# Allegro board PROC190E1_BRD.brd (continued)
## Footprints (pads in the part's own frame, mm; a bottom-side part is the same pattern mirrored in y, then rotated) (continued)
DIO_DFN0201_0-4
  rect 0.229x0.381 smd: 1(-0.22,0) 2(0.22,0)
DIO_DFN0402_0-5
  rect 0.356x0.61 smd: 1(-0.34,0) 2(0.34,0)
DIO_SOT23_123
  rect 1.016x0.61 smd: 1(-1.15,0.95) 2(-1.15,-0.95) 3(1.15,0)
DIO_SOT323-3_1-1
  rect 0.838x0.457 smd: 1(-1.05,0.65) 2(-1.05,-0.65) 3(1.05,0)
DSBGA12_15-74_60X70_0-4
  round 0.279 smd: A1(-0.4,0.6) A2(0,0.6) A3(0.4,0.6) B1(-0.4,0.2) B2(0,0.2) B3(0.4,0.2) C1(-0.4,-0.2) C2(0,-0.2) C3(0.4,-0.2) D1(-0.4,-0.6) D2(0,-0.6) D3(0.4,-0.6)
EMIFIL_BLM15A_0402_0-6
  rect 0.61x0.61 smd: 1(-0.46,0) 2(0.46,0)
EMIFIL_BLM18K_0603
  rect 0.94x1.194 smd: 1(-0.825,0) 2(0.825,0)
EMIFIL_BLM18P_0603_0-8
  rect 0.991x0.991 smd: 1(-0.75,0) 2(0.75,0)
HDR_1X2_90120-0122_S_T_5-6
  rect 1.702x1.702 hole 1.016: 1(0,0)
  round 1.702 hole 1.016: 2(-2.54,0)
HDR_1X2_61300211121_S_T_8-6
  rect 1.803x1.803 hole 1.118: 1(0,0)
  round 1.803 hole 1.118: 2(-2.54,0)
HDR_1X3_100_S_T
  rect 1.803x1.803 hole 1.118: 1(0,0)
  round 1.803 hole 1.118: 2(-2.54,0) 3(-5.08,0)
HDR_1X3_87224-3_S_T_10-8
  rect 1.6x1.6 hole 0.914: 1(0,0)
  round 1.6 hole 0.914: 2(-2.54,0) 3(-5.08,0)
HDR_2X4_90131-07_S_T_9-5
  rect 1.702x1.702 hole 1.016: 1(0,0)
  round 1.702 hole 1.016: 2(0,2.54) 3(2.54,0) 4(2.54,2.54) 5(5.08,0) 6(5.08,2.54) 7(7.62,0) 8(7.62,2.54)
HDR_2X5_PEC05DAAN_S_T_8-6
  rect 1.702x1.702 hole 1.016: 1(0,0)
  round 1.702 hole 1.016: 2(0,2.54) 3(2.54,0) 4(2.54,2.54) 5(5.08,0) 6(5.08,2.54) 7(7.62,0) 8(7.62,2.54) 9(10.16,0) 10(10.16,2.54)
HDR_2X10_FTR-110-51-D-06_S_S_8-7
  rect 0.711x3.124 smd: 1(-5.715,-2.578) 2(-5.715,2.578) 3(-4.445,-2.578) 4(-4.445,2.578) 5(-3.175,-2.578) 7(-1.905,-2.578) 8(-1.905,2.578) 9(-0.635,-2.578) 10(-0.635,2.578) 11(0.635,-2.578) 12(0.635,2.578) 13(1.905,-2.578) 14(1.905,2.578) 15(3.175,-2.578) 16(3.175,2.578) 17(4.445,-2.578) 18(4.445,2.578) 19(5.715,-2.578) 20(5.715,2.578)
HDR_6X2_100_S_T_5-5
  rect 1.702x1.702 hole 1.016: 1(0,0)
  round 1.702 hole 1.016: 2(0,2.54) 3(2.54,0) 4(2.54,2.54) 5(5.08,0) 6(5.08,2.54) 7(7.62,0) 8(7.62,2.54) 9(10.16,0) 10(10.16,2.54) 11(12.7,0) 12(12.7,2.54)
IND4_DLW21H_90X60_SMD_1-4
  rect 0.889x0.356 smd: 1(-0.85,-0.425) 2(0.85,-0.425) 3(0.85,0.425) 4(-0.85,0.425)
IND0806
  rect 1.219x1.803 smd: 1(-0.85,0) 2(0.85,0)
IND0806_1-2
  rect 1.219x1.803 smd: 1(-0.85,0) 2(0.85,0)
IND1210_1-2
  rect 1.346x2.794 smd: 1(-1.6,0) 2(1.6,0)
IND_XAL8080_330X350_SMD_8
  rect 1.778x7.01 smd: 1(-2.58,0) 2(2.58,0)
LED_150040GS73220_40X20_SMD_0-4
  rect 0.406x0.457 smd: 1(-0.5,0) 2(0.5,0)
LED_150080VS75000_80X50_SMD_0-8
  rect 1.092x1.194 smd: 1(-1.05,0) 2(1.05,0)
LED_150080VS75000_80X50_SMD_0-8#2
  rect 1.092x1.194 smd: 1(-1.05,0) 2(1.05,0)
LQFP64_19-68_390X390_1-6
  rect 1.499x0.305 smd: 1(-5.7,3.75) 2(-5.7,3.25) 3(-5.7,2.75) 4(-5.7,2.25) 5(-5.7,1.75) 6(-5.7,1.25) 7(-5.7,0.75) 8(-5.7,0.25) 9(-5.7,-0.25) 10(-5.7,-0.75) 11(-5.7,-1.25) 12(-5.7,-1.75) 13(-5.7,-2.25) 14(-5.7,-2.75) 15(-5.7,-3.25) 16(-5.7,-3.75) 33(5.7,-3.75) 34(5.7,-3.25) 35(5.7,-2.75) 36(5.7,-2.25) 37(5.7,-1.75) 38(5.7,-1.25) 39(5.7,-0.75) 40(5.7,-0.25) 41(5.7,0.25) 42(5.7,0.75) 43(5.7,1.25) 44(5.7,1.75) 45(5.7,2.25) 46(5.7,2.75) 47(5.7,3.25) 48(5.7,3.75)
  rect 0.305x1.499 smd: 17(-3.75,-5.7) 18(-3.25,-5.7) 19(-2.75,-5.7) 20(-2.25,-5.7) 21(-1.75,-5.7) 22(-1.25,-5.7) 23(-0.75,-5.7) 24(-0.25,-5.7) 25(0.25,-5.7) 26(0.75,-5.7) 27(1.25,-5.7) 28(1.75,-5.7) 29(2.25,-5.7) 30(2.75,-5.7) 31(3.25,-5.7) 32(3.75,-5.7) 49(3.75,5.7) 50(3.25,5.7) 51(2.75,5.7) 52(2.25,5.7) 53(1.75,5.7) 54(1.25,5.7) 55(0.75,5.7) 56(0.25,5.7) 57(-0.25,5.7) 58(-0.75,5.7) 59(-1.25,5.7) 60(-1.75,5.7) 61(-2.25,5.7) 62(-2.75,5.7) 63(-3.25,5.7) 64(-3.75,5.7)
MSOP8_25-59_125X125_1-1
  rect 1.448x0.457 smd: 1(-2.2,0.975) 2(-2.2,0.325) 3(-2.2,-0.325) 4(-2.2,-0.975) 5(2.2,-0.975) 6(2.2,-0.325) 7(2.2,0.325) 8(2.2,0.975)
MSOP10_19-68_120X120_1-1
  rect 1.448x0.305 smd: 1(-2.2,1) 2(-2.2,0.5) 3(-2.2,0) 4(-2.2,-0.5) 5(-2.2,-1) 6(2.2,-1) 7(2.2,-0.5) 8(2.2,0) 9(2.2,0.5) 10(2.2,1)
QFN24_19-68_220X140_1
  rect 0.838x0.279 smd: 1(-2.725,-0.75) 12(2.725,-0.75) 13(2.725,0.75) 24(-2.725,0.75)
  rect 0.279x0.838 smd: 2(-2.25,-1.725) 3(-1.75,-1.725) 4(-1.25,-1.725) 5(-0.75,-1.725) 6(-0.25,-1.725) 7(0.25,-1.725) 8(0.75,-1.725) 9(1.25,-1.725) 10(1.75,-1.725) 11(2.25,-1.725) 14(2.25,1.725) 15(1.75,1.725) 16(1.25,1.725) 17(0.75,1.725) 18(0.25,1.725) 19(-0.25,1.725) 20(-0.75,1.725) 21(-1.25,1.725) 22(-1.75,1.725) 23(-2.25,1.725)
  custom 0.508x0.508 smd: 25(0,0)
QFN24_TAD5212IRGER_160X160_1
  rect 0.787x0.305 smd: 1(-2,1.25) 2(-2,0.75) 3(-2,0.25) 4(-2,-0.25) 5(-2,-0.75) 6(-2,-1.25) 13(2,-1.25) 14(2,-0.75) 15(2,-0.25) 16(2,0.25) 17(2,0.75) 18(2,1.25)
  rect 0.305x0.787 smd: 7(-1.25,-2) 8(-0.75,-2) 9(-0.25,-2) 10(0.25,-2) 11(0.75,-2) 12(1.25,-2) 19(1.25,2) 20(0.75,2) 21(0.25,2) 22(-0.25,2) 23(-0.75,2) 24(-1.25,2)
  rect 2.21x2.21 smd: 25(0,0)
  rect 0.254x0.254 smd: A1(-1.725,1.725) A2(-1.725,-1.725) A3(1.725,-1.725) A4(1.725,1.725)
QFN32_19-68_200X200
  rect 0.838x0.305 smd: 1(-2.5,1.75) 2(-2.5,1.25) 3(-2.5,0.75) 4(-2.5,0.25) 5(-2.5,-0.25) 6(-2.5,-0.75) 7(-2.5,-1.25) 8(-2.5,-1.75) 17(2.5,-1.75) 18(2.5,-1.25) 19(2.5,-0.75) 20(2.5,-0.25) 21(2.5,0.25) 22(2.5,0.75) 23(2.5,1.25) 24(2.5,1.75)
  rect 0.305x0.838 smd: 9(-1.75,-2.5) 10(-1.25,-2.5) 11(-0.75,-2.5) 12(-0.25,-2.5) 13(0.25,-2.5) 14(0.75,-2.5) 15(1.25,-2.5) 16(1.75,-2.5) 25(1.75,2.5) 26(1.25,2.5) 27(0.75,2.5) 28(0.25,2.5) 29(-0.25,2.5) 30(-0.75,2.5) 31(-1.25,2.5) 32(-1.75,2.5)
  rect 3.556x3.556 smd: 33(0,0)
QFN32_19-68_200X200_0-8_EP3-6
  rect 0.787x0.305 smd: 1(-2.5,1.75) 2(-2.5,1.25) 3(-2.5,0.75) 4(-2.5,0.25) 5(-2.5,-0.25) 6(-2.5,-0.75) 7(-2.5,-1.25) 8(-2.5,-1.75) 17(2.5,-1.75) 18(2.5,-1.25) 19(2.5,-0.75) 20(2.5,-0.25) 21(2.5,0.25) 22(2.5,0.75) 23(2.5,1.25) 24(2.5,1.75)
  rect 0.305x0.787 smd: 9(-1.75,-2.5) 10(-1.25,-2.5) 11(-0.75,-2.5) 12(-0.25,-2.5) 13(0.25,-2.5) 14(0.75,-2.5) 15(1.25,-2.5) 16(1.75,-2.5) 25(1.75,2.5) 26(1.25,2.5) 27(0.75,2.5) 28(0.25,2.5) 29(-0.25,2.5) 30(-0.75,2.5) 31(-1.25,2.5) 32(-1.75,2.5)
  rect 3.607x3.607 smd: 33(0,0)
RES0201_0-5
  rect 0.356x0.33 smd: 1(-0.28,0) 2(0.28,0)
RES0402_0-5
  rect 0.559x0.635 smd: 1(-0.49,0) 2(0.49,0)
RES0603_0-5
  rect 0.635x0.991 smd: 1(-0.74,0) 2(0.74,0)
RES0603_0-75
  rect 0.635x0.991 smd: 1(-0.74,0) 2(0.74,0)
RES0805_0-75
  rect 1.194x1.448 smd: 1(-0.95,0) 2(0.95,0)
RES_CST0612_0612-4_0-9
  rect 0.991x2.311 smd: 1(-0.85,0.6) 4(0.85,0.6)
  rect 0.991x0.787 smd: 2(-0.85,-1.35) 3(0.85,-1.35)
RES_KRL3216T4_1206-4_0-7
  rect 1.143x0.356 smd: 1(-0.775,1.5) 4(0.775,1.5)
  rect 1.143x2.692 smd: 2(-0.775,-0.325) 3(0.775,-0.325)
RESA_EXB_0201-4_0-5
  rect 0.203x0.305 smd: 1(-0.6,-0.275) 2(-0.2,-0.275) 3(0.2,-0.275) 4(0.6,-0.275) 5(0.6,0.275) 6(0.2,0.275) 7(-0.2,0.275) 8(-0.6,0.275)
SC70-5
  rect 0.94x0.406 smd: 1(-1.1,0.65) 2(-1.1,0) 3(-1.1,-0.65) 4(1.1,-0.65) 5(1.1,0.65)
SC70-5_1-1
  rect 0.94x0.406 smd: 1(-1.1,0.65) 2(-1.1,0) 3(-1.1,-0.65) 4(1.1,-0.65) 5(1.1,0.65)
SC70-5_1-1#2
  rect 0.762x0.406 smd: 1(-1,0.65) 2(-1,0) 3(-1,-0.65) 4(1,-0.65) 5(1,0.65)
SC70-6_1-1
  rect 0.762x0.406 smd: 1(-1,0.65) 2(-1,0) 3(-1,-0.65) 4(1,-0.65) 5(1,0) 6(1,0.65)
SOIC8_1-8
  rect 1.549x0.61 smd: 1(-2.7,1.905) 2(-2.7,0.635) 3(-2.7,-0.635) 4(-2.7,-1.905) 5(2.7,-1.905) 6(2.7,-0.635) 7(2.7,0.635) 8(2.7,1.905)
SON6_19-68_40X60_PB_0-6
  rect 0.356x0.305 smd: 1(-0.3,0.5) 2(-0.3,0) 3(-0.3,-0.5) 4(0.3,-0.5) 5(0.3,0) 6(0.3,0.5)
SON6_25-59_85X85
  rect 0.61x0.356 smd: 1(-1.05,0.65) 2(-1.05,0) 3(-1.05,-0.65) 4(1.05,-0.65) 5(1.05,0) 6(1.05,0.65)
  rect 1.092x1.702 smd: 7(0,0)
SON6_25-59_85X85_0-8
  rect 0.61x0.356 smd: 1(-1.05,0.65) 2(-1.05,0) 3(-1.05,-0.65) 4(1.05,-0.65) 5(1.05,0) 6(1.05,0.65)
  rect 1.067x1.702 smd: 7(0,0)
SON6_25-59_85X85_0-8#2
  rect 0.61x0.356 smd: 1(-1.05,0.65) 2(-1.05,0) 3(-1.05,-0.65) 4(1.05,-0.65) 5(1.05,0) 6(1.05,0.65)
  rect 1.067x1.702 smd: 7(0,0)
SON6_CSD17313Q2_80X80
  rect 0.406x0.457 smd: 1(-0.65,-0.923) 2(0,-0.923) 3(0.65,-0.923) 4(0.65,0.923) 5(0,0.923) 6(-0.65,0.923)
  rect 0.406x0.864 smd: 7(0.65,0.096)
  rect 1.041x1.092 smd: 8(-0.325,0)
SON6_SN74LVC2G17_40X60_0-6
  rect 0.356x0.203 smd: 1(-0.275,0.5)
  rect 0.305x0.203 smd: 2(-0.3,0) 3(-0.3,-0.5) 4(0.3,-0.5) 5(0.3,0) 6(0.3,0.5)
SON8_25-59_130X130_1
  rect 0.762x0.356 smd: 1(-1.45,0.975) 2(-1.45,0.325) 3(-1.45,-0.325) 4(-1.45,-0.975) 5(1.45,-0.975) 6(1.45,-0.325) 7(1.45,0.325) 8(1.45,0.975)
  rect 1.753x2.515 smd: 9(0,0)
SOT23-5
  rect 0.889x0.559 smd: 1(-1.2,0.95) 2(-1.2,0) 3(-1.2,-0.95) 4(1.2,-0.95) 5(1.2,0.95)
SOT23-5#2
  rect 1.092x0.61 smd: 1(-1.3,0.95) 2(-1.3,0) 3(-1.3,-0.95) 4(1.3,-0.95) 5(1.3,0.95)
SOT23-5_1-5
  rect 1.092x0.61 smd: 1(-1.3,0.95) 2(-1.3,0) 3(-1.3,-0.95) 4(1.3,-0.95) 5(1.3,0.95)
SOT23-6
  rect 1.041x0.61 smd: 1(-1.35,0.95) 2(-1.35,0) 3(-1.35,-0.95) 4(1.35,-0.95) 5(1.35,0) 6(1.35,0.95)
SOT23-14_1-1
  rect 1.041x0.305 smd: 1(-1.5,1.5) 2(-1.5,1) 3(-1.5,0.5) 4(-1.5,0) 5(-1.5,-0.5) 6(-1.5,-1) 7(-1.5,-1.5) 8(1.5,-1.5) 9(1.5,-1) 10(1.5,-0.5) 11(1.5,0) 12(1.5,0.5) 13(1.5,1) 14(1.5,1.5)
SOT23-123_1-2
  rect 1.016x0.61 smd: 1(-1.15,0.95) 2(-1.15,-0.95) 3(1.15,0)
SOT553-5_0-6
  rect 0.559x0.229 smd: 1(-0.69,0.5) 2(-0.69,0) 3(-0.69,-0.5) 4(0.69,-0.5) 5(0.69,0.5)
SW3_CAS-120TA_215X100_SMD
  rect 1.6x1.016 smd: 1(-1.75,-1.15) 2(0,1.15) 3(1.75,-1.15)
SW4_49-99_150X230_SMD_2-7
  rect 0.762x1.27 smd: 1(-0.635,-3.81) 2(0.635,-3.81) 3(0.635,3.81) 4(-0.635,3.81)
SW4_100X216_200X200_SMD_4-2
  rect 1.27x1.27 smd: 1(-1.27,-2.75) 2(1.27,-2.75) 3(1.27,2.75) 4(-1.27,2.75)
SW4_100X216_200X200_SMD_4-2#2
  rect 1.27x1.27 smd: 1(-1.27,-2.75) 2(1.27,-2.75) 3(1.27,2.75) 4(-1.27,2.75)
SW16_416131160808_460X230_SMD_2-7
  rect 0.762x1.27 smd: 1(-4.445,-3.81) 2(-3.175,-3.81) 3(-1.905,-3.81) 4(-0.635,-3.81) 5(0.635,-3.81) 6(1.905,-3.81) 7(3.175,-3.81) 8(4.445,-3.81) 9(4.445,3.81) 10(3.175,3.81) 11(1.905,3.81) 12(0.635,3.81) 13(-0.635,3.81) 14(-1.905,3.81) 15(-3.175,3.81) 16(-4.445,3.81)
SW_TDA01H0S_240X90_SMD_2-3
  rect 1.27x0.762 smd: 1(-3.81,0) 2(3.81,0)
TO_SOT23-123
  rect 1.016x1.397 smd: 1(-0.95,-1.1) 2(0.95,-1.1) 3(0,1.1)
TP20_SMD
  round 0.508 smd: 1(0,0)
TP30_SMD
  round 0.762 smd: 1(0,0)
TP40_SMD
  round 1.016 smd: 1(0,0)
TP_40X65
  round 1.651 hole 1.016: 1(0,0)
TQFN42_19-68_140X360_0-8
  rect 0.813x0.305 smd: 1(-1.7,4) 2(-1.7,3.5) 3(-1.7,3) 4(-1.7,2.5) 5(-1.7,2) 6(-1.7,1.5) 7(-1.7,1) 8(-1.7,0.5) 9(-1.7,0) 10(-1.7,-0.5) 11(-1.7,-1) 12(-1.7,-1.5) 13(-1.7,-2) 14(-1.7,-2.5) 15(-1.7,-3) 16(-1.7,-3.5) 17(-1.7,-4) 22(1.7,-4) 23(1.7,-3.5) 24(1.7,-3) 25(1.7,-2.5) 26(1.7,-2) 27(1.7,-1.5) 28(1.7,-1) 29(1.7,-0.5) 30(1.7,0) 31(1.7,0.5) 32(1.7,1) 33(1.7,1.5) 34(1.7,2) 35(1.7,2.5) 36(1.7,3) 37(1.7,3.5) 38(1.7,4)
  rect 0.305x0.813 smd: 18(-0.75,-4.45) 19(-0.25,-4.45) 20(0.25,-4.45) 21(0.75,-4.45) 39(0.75,4.45) 40(0.25,4.45) 41(-0.25,4.45) 42(-0.75,4.45)
  rect 2.159x7.645 smd: 43(0,0)
TQFP128_15-74_550X550_1-2
  rect 1.499x0.203 smd: 1(-7.7,6.2) 2(-7.7,5.8) 3(-7.7,5.4) 4(-7.7,5) 5(-7.7,4.6) 6(-7.7,4.2) 7(-7.7,3.8) 8(-7.7,3.4) 9(-7.7,3) 10(-7.7,2.6) 11(-7.7,2.2) 12(-7.7,1.8) 13(-7.7,1.4) 14(-7.7,1) 15(-7.7,0.6) 16(-7.7,0.2) 17(-7.7,-0.2) 18(-7.7,-0.6) 19(-7.7,-1) 20(-7.7,-1.4) 21(-7.7,-1.8) 22(-7.7,-2.2) 23(-7.7,-2.6) 24(-7.7,-3) 25(-7.7,-3.4) 26(-7.7,-3.8) 27(-7.7,-4.2) 28(-7.7,-4.6) 29(-7.7,-5) 30(-7.7,-5.4) 31(-7.7,-5.8) 32(-7.7,-6.2) 65(7.7,-6.2) 66(7.7,-5.8) 67(7.7,-5.4) 68(7.7,-5) 69(7.7,-4.6) 70(7.7,-4.2) 71(7.7,-3.8) 72(7.7,-3.4) 73(7.7,-3) 74(7.7,-2.6) 75(7.7,-2.2) 76(7.7,-1.8) 77(7.7,-1.4) 78(7.7,-1) 79(7.7,-0.6) 80(7.7,-0.2) 81(7.7,0.2) 82(7.7,0.6) 83(7.7,1) 84(7.7,1.4) 85(7.7,1.8) 86(7.7,2.2) 87(7.7,2.6) 88(7.7,3) 89(7.7,3.4) 90(7.7,3.8) 91(7.7,4.2) 92(7.7,4.6) 93(7.7,5) 94(7.7,5.4) 95(7.7,5.8) 96(7.7,6.2)
  rect 0.203x1.499 smd: 33(-6.2,-7.7) 34(-5.8,-7.7) 35(-5.4,-7.7) 36(-5,-7.7) 37(-4.6,-7.7) 38(-4.2,-7.7) 39(-3.8,-7.7) 40(-3.4,-7.7) 41(-3,-7.7) 42(-2.6,-7.7) 43(-2.2,-7.7) 44(-1.8,-7.7) 45(-1.4,-7.7) 46(-1,-7.7) 47(-0.6,-7.7) 48(-0.2,-7.7) 49(0.2,-7.7) 50(0.6,-7.7) 51(1,-7.7) 52(1.4,-7.7) 53(1.8,-7.7) 54(2.2,-7.7) 55(2.6,-7.7) 56(3,-7.7) 57(3.4,-7.7) 58(3.8,-7.7) 59(4.2,-7.7) 60(4.6,-7.7) 61(5,-7.7) 62(5.4,-7.7) 63(5.8,-7.7) 64(6.2,-7.7) 97(6.2,7.7) 98(5.8,7.7) 99(5.4,7.7) 100(5,7.7) 101(4.6,7.7) 102(4.2,7.7) 103(3.8,7.7) 104(3.4,7.7) 105(3,7.7) 106(2.6,7.7) 107(2.2,7.7) 108(1.8,7.7) 109(1.4,7.7) 110(1,7.7) 111(0.6,7.7) 112(0.2,7.7) 113(-0.2,7.7) 114(-0.6,7.7) 115(-1,7.7) 116(-1.4,7.7) 117(-1.8,7.7) 118(-2.2,7.7) 119(-2.6,7.7) 120(-3,7.7) 121(-3.4,7.7) 122(-3.8,7.7) 123(-4.2,7.7) 124(-4.6,7.7) 125(-5,7.7) 126(-5.4,7.7) 127(-5.8,7.7) 128(-6.2,7.7)
TSSOP8_25-59_125X180_1-2
  rect 1.499x0.457 smd: 1(-2.9,0.975) 2(-2.9,0.325) 3(-2.9,-0.325) 4(-2.9,-0.975) 5(2.9,-0.975) 6(2.9,-0.325) 7(2.9,0.325) 8(2.9,0.975)
TSSOP14_25-59_205X180_1-2
  rect 1.499x0.457 smd: 1(-2.9,1.95) 2(-2.9,1.3) 3(-2.9,0.65) 4(-2.9,0) 5(-2.9,-0.65) 6(-2.9,-1.3) 7(-2.9,-1.95) 8(2.9,-1.95) 9(2.9,-1.3) 10(2.9,-0.65) 11(2.9,0) 12(2.9,0.65) 13(2.9,1.3) 14(2.9,1.95)
TSSOP20_25-59_260X180
  rect 1.499x0.457 smd: 1(-2.9,2.925) 2(-2.9,2.275) 3(-2.9,1.625) 4(-2.9,0.975) 5(-2.9,0.325) 6(-2.9,-0.325) 7(-2.9,-0.975) 8(-2.9,-1.625) 9(-2.9,-2.275) 10(-2.9,-2.925) 11(2.9,-2.925) 12(2.9,-2.275) 13(2.9,-1.625) 14(2.9,-0.975) 15(2.9,-0.325) 16(2.9,0.325) 17(2.9,0.975) 18(2.9,1.625) 19(2.9,2.275) 20(2.9,2.925)
TSSOP56_19-68_560X240_1-2
  rect 1.499x0.305 smd: 1(-3.75,6.75) 2(-3.75,6.25) 3(-3.75,5.75) 4(-3.75,5.25) 5(-3.75,4.75) 6(-3.75,4.25) 7(-3.75,3.75) 8(-3.75,3.25) 9(-3.75,2.75) 10(-3.75,2.25) 11(-3.75,1.75) 12(-3.75,1.25) 13(-3.75,0.75) 14(-3.75,0.25) 15(-3.75,-0.25) 16(-3.75,-0.75) 17(-3.75,-1.25) 18(-3.75,-1.75) 19(-3.75,-2.25) 20(-3.75,-2.75) 21(-3.75,-3.25) 22(-3.75,-3.75) 23(-3.75,-4.25) 24(-3.75,-4.75) 25(-3.75,-5.25) 26(-3.75,-5.75) 27(-3.75,-6.25) 28(-3.75,-6.75) 29(3.75,-6.75) 30(3.75,-6.25) 31(3.75,-5.75) 32(3.75,-5.25) 33(3.75,-4.75) 34(3.75,-4.25) 35(3.75,-3.75) 36(3.75,-3.25) 37(3.75,-2.75) 38(3.75,-2.25) 39(3.75,-1.75) 40(3.75,-1.25) 41(3.75,-0.75) 42(3.75,-0.25) 43(3.75,0.25) 44(3.75,0.75) 45(3.75,1.25) 46(3.75,1.75) 47(3.75,2.25) 48(3.75,2.75) 49(3.75,3.25) 50(3.75,3.75) 51(3.75,4.25) 52(3.75,4.75) 53(3.75,5.25) 54(3.75,5.75) 55(3.75,6.25) 56(3.75,6.75)
TVSOP14_15-74_180X150_1-2
  rect 1.499x0.203 smd: 1(-2.9,1.2) 2(-2.9,0.8) 3(-2.9,0.4) 4(-2.9,0) 5(-2.9,-0.4) 6(-2.9,-0.8) 7(-2.9,-1.2) 8(2.9,-1.2) 9(2.9,-0.8) 10(2.9,-0.4) 11(2.9,0) 12(2.9,0.4) 13(2.9,0.8) 14(2.9,1.2)
unnamed
  round 3.073 hole 3.2 unplated: (0,0)
unnamed#2
  round 0.686 hole 0.813 unplated: (-1.27,1.076) (0,1.076) (1.27,1.076)
UQFN10_19-68_80X60_0-6
  rect 0.584x0.305 smd: 1(-0.635,0.75) 4(-0.635,-0.75) 6(0.635,-0.75) 9(0.635,0.75)
  rect 0.584x0.254 smd: 2(-0.635,0.25) 3(-0.635,-0.25) 7(0.635,-0.25) 8(0.635,0.25)
  rect 0.305x0.635 smd: 5(0,-0.86) 10(0,0.86)
UQFN16_TMUX1574_70X100_0-6
  rect 0.711x0.203 smd: 1(-0.75,0.6)
  rect 0.61x0.203 smd: 2(-0.8,0.2) 3(-0.8,-0.2) 4(-0.8,-0.6) 9(0.8,-0.6) 10(0.8,-0.2) 11(0.8,0.2) 12(0.8,0.6)
  rect 0.203x0.61 smd: 5(-0.6,-1.2) 6(-0.2,-1.2) 7(0.2,-1.2) 8(0.6,-1.2) 13(0.6,1.2) 14(0.2,1.2) 15(-0.2,1.2) 16(-0.6,1.2)
UQFN16_TMUX1574_70X100_0-6#2
  rect 0.711x0.203 smd: 1(-0.75,0.6)
  rect 0.61x0.203 smd: 2(-0.8,0.2) 3(-0.8,-0.2) 4(-0.8,-0.6) 9(0.8,-0.6) 10(0.8,-0.2) 11(0.8,0.2) 12(0.8,0.6)
  rect 0.203x0.61 smd: 5(-0.6,-1.2) 6(-0.2,-1.2) 7(0.2,-1.2) 8(0.6,-1.2) 13(0.6,1.2) 14(0.2,1.2) 15(-0.2,1.2) 16(-0.6,1.2)
USON10_TMUX1204_40X100_0-6
  rect 0.559x0.203 smd: 1(-0.417,1) 2(-0.417,0.5) 4(-0.417,-0.5) 5(-0.417,-1) 6(0.417,-1) 7(0.417,-0.5) 9(0.417,0.5) 10(0.417,1)
  rect 0.559x0.406 smd: 3(-0.417,0) 8(0.417,0)
USON10_TPD4E05U_40X100_0-6
  rect 0.559x0.305 smd: 1(-0.385,1) 2(-0.385,0.5) 4(-0.385,-0.5) 5(-0.385,-1) 6(0.385,-1) 7(0.385,-0.5) 9(0.385,0.5) 10(0.385,1)
  rect 0.559x0.406 smd: 3(-0.385,0) 8(0.385,0)
VFBGA153_19-68_460X520_0-9
  round 0.203 smd: A1(-3.25,3.25) A2(-2.75,3.25) A3(-2.25,3.25) A4(-1.75,3.25) A5(-1.25,3.25) A6(-0.75,3.25) B1(-3.25,2.75) C1(-3.25,2.25) D1(-3.25,1.75) M1(-3.25,-2.25) N1(-3.25,-2.75) P1(-3.25,-3.25)
  round 0.254 smd: A7(-0.25,3.25) A8(0.25,3.25) A9(0.75,3.25) A10(1.25,3.25) A11(1.75,3.25) A12(2.25,3.25) A13(2.75,3.25) A14(3.25,3.25) B2(-2.75,2.75) B3(-2.25,2.75) B4(-1.75,2.75) B5(-1.25,2.75) B6(-0.75,2.75) B7(-0.25,2.75) B8(0.25,2.75) B9(0.75,2.75) B10(1.25,2.75) B11(1.75,2.75) B12(2.25,2.75) B13(2.75,2.75) B14(3.25,2.75) C2(-2.75,2.25) C3(-2.25,2.25) C4(-1.75,2.25) C5(-1.25,2.25) C6(-0.75,2.25) C7(-0.25,2.25) C8(0.25,2.25) C9(0.75,2.25) C10(1.25,2.25) C11(1.75,2.25) C12(2.25,2.25) C13(2.75,2.25) C14(3.25,2.25) D2(-2.75,1.75) D3(-2.25,1.75) D4(-1.75,1.75) D12(2.25,1.75) D13(2.75,1.75) D14(3.25,1.75) E1(-3.25,1.25) E2(-2.75,1.25) E3(-2.25,1.25) E5(-1.25,1.25) E6(-0.75,1.25) E7(-0.25,1.25) E8(0.25,1.25) E9(0.75,1.25) E10(1.25,1.25) E12(2.25,1.25) E13(2.75,1.25) E14(3.25,1.25) F1(-3.25,0.75) F2(-2.75,0.75) F3(-2.25,0.75) F5(-1.25,0.75) F10(1.25,0.75) F12(2.25,0.75) F13(2.75,0.75) F14(3.25,0.75) G1(-3.25,0.25) G2(-2.75,0.25) G3(-2.25,0.25) G5(-1.25,0.25) G10(1.25,0.25) G12(2.25,0.25) G13(2.75,0.25) G14(3.25,0.25) H1(-3.25,-0.25) H2(-2.75,-0.25) H3(-2.25,-0.25) H5(-1.25,-0.25) H10(1.25,-0.25) H12(2.25,-0.25) H13(2.75,-0.25) H14(3.25,-0.25) J1(-3.25,-0.75) J2(-2.75,-0.75) J3(-2.25,-0.75) J5(-1.25,-0.75) J10(1.25,-0.75) J12(2.25,-0.75) J13(2.75,-0.75) J14(3.25,-0.75) K1(-3.25,-1.25) K2(-2.75,-1.25) K3(-2.25,-1.25) K5(-1.25,-1.25) K6(-0.75,-1.25) K7(-0.25,-1.25) K8(0.25,-1.25) K9(0.75,-1.25) K10(1.25,-1.25) K12(2.25,-1.25) K13(2.75,-1.25) K14(3.25,-1.25) L1(-3.25,-1.75) L2(-2.75,-1.75) L3(-2.25,-1.75) L12(2.25,-1.75) L13(2.75,-1.75) L14(3.25,-1.75) M2(-2.75,-2.25) M3(-2.25,-2.25) M4(-1.75,-2.25) M5(-1.25,-2.25) M6(-0.75,-2.25) M7(-0.25,-2.25) M8(0.25,-2.25) M9(0.75,-2.25) M10(1.25,-2.25) M11(1.75,-2.25) M12(2.25,-2.25) M13(2.75,-2.25) M14(3.25,-2.25) N2(-2.75,-2.75) N3(-2.25,-2.75) N4(-1.75,-2.75) N5(-1.25,-2.75) N6(-0.75,-2.75) N7(-0.25,-2.75) N8(0.25,-2.75) N9(0.75,-2.75) N10(1.25,-2.75) N11(1.75,-2.75) N12(2.25,-2.75) N13(2.75,-2.75) N14(3.25,-2.75) P2(-2.75,-3.25) P3(-2.25,-3.25) P4(-1.75,-3.25) P5(-1.25,-3.25) P6(-0.75,-3.25) P7(-0.25,-3.25) P8(0.25,-3.25) P9(0.75,-3.25) P10(1.25,-3.25) P11(1.75,-3.25) P12(2.25,-3.25) P13(2.75,-3.25) P14(3.25,-3.25)
VQFN56_TPS65987D_280X280_1
  rect 0.813x0.711 smd: 1(-3.35,2.4) 3(-3.35,1.6) 11(-3.35,-1.6) 13(-3.35,-2.4)
  rect 0.711x0.203 smd: 5(-3.35,1) 6(-3.35,0.6) 7(-3.35,0.2) 8(-3.35,-0.2) 9(-3.35,-0.6) 10(-3.35,-1) 29(3.35,-2.6) 30(3.35,-2.2) 31(3.35,-1.8) 32(3.35,-1.4) 33(3.35,-1) 34(3.35,-0.6) 35(3.35,-0.2) 36(3.35,0.2) 37(3.35,0.6) 38(3.35,1) 39(3.35,1.4) 40(3.35,1.8) 41(3.35,2.2) 42(3.35,2.6)
  rect 0.203x0.711 smd: 15(-2.6,-3.35) 16(-2.2,-3.35) 17(-1.8,-3.35) 18(-1.4,-3.35) 19(-1,-3.35) 20(-0.6,-3.35) 21(-0.2,-3.35) 22(0.2,-3.35) 23(0.6,-3.35) 24(1,-3.35) 25(1.4,-3.35) 26(1.8,-3.35) 27(2.2,-3.35) 28(2.6,-3.35) 43(2.6,3.35) 44(2.2,3.35) 45(1.8,3.35) 46(1.4,3.35) 47(1,3.35) 48(0.6,3.35) 49(0.2,3.35) 50(-0.2,3.35) 51(-0.6,3.35) 52(-1,3.35) 53(-1.4,3.35) 54(-1.8,3.35) 55(-2.2,3.35) 56(-2.6,3.35)
  rect 1.753x2.591 smd: 57(-1.875,1.45)
  rect 1.753x2.54 smd: 58(-1.875,-1.475)
  rect 3.404x5.512 smd: 59(1.05,0)
VQFN-HR36-35_TPS65224_240X200_1
  custom 0.206x0.206 smd: 1(-2.5,2) 9(-2.5,-2) 19(2.5,-2) 27(2.5,2)
  rect 0.838x0.254 smd: 2(-2.775,1.5) 8(-2.775,-1.5) 20(2.775,-1.5) 26(2.775,1.5)
  rect 0.914x0.254 smd: 3(-2.738,1) 7(-2.738,-1) 21(2.738,-1) 25(2.738,1)
  rect 1.041x0.254 smd: 4(-2.675,0.5) 6(-2.675,-0.5) 22(2.675,-0.5) 24(2.675,0.5)
  custom 0.3x0.3 smd: 5(0,0)
  rect 0.254x0.838 smd: 10(-2,-2.275) 11(-1.5,-2.275) 17(1.5,-2.275) 18(2,-2.275) 28(2,2.275) 29(1.5,2.275) 35(-1.5,2.275) 36(-2,2.275)
  rect 0.254x0.914 smd: 12(-1,-2.237) 13(-0.5,-2.237) 15(0.5,-2.237) 16(1,-2.237) 30(1,2.237) 31(0.5,2.237) 33(-0.5,2.237) 34(-1,2.237)
  rect 0.254x1.702 smd: 14(0,-1.85) 32(0,1.85)
VQFNHR14_LM61460_160X140_1
  custom 0.175x0.175 smd: 1(-1.675,1.15) 5(-1.675,-1.15)
  rect 0.711x0.254 smd: 2(-1.85,0.525) 4(-1.85,-0.525)
  rect 0.711x0.305 smd: 3(-1.85,0)
  rect 0.254x0.711 smd: 6(-1.125,-1.6) 7(-0.625,-1.6) 13(-0.625,1.6) 14(-1.125,1.6)
  rect 0.406x0.991 smd: 8(0.45,-1.45) 12(0.45,1.45)
  custom 0.2x0.2 smd: 9(1.6,-1.15) 11(1.6,1.15)
  rect 2.388x0.406 smd: 10(1,0)
VSON4_LMK6CE_80X100_SMD_1
  rect 0.889x0.66 smd: 1(-0.749,0.826) 2(-0.749,-0.826) 3(0.749,-0.826) 4(0.749,0.826)
VSONHR6_TPS62826_60X60_1
  rect 0.711x0.356 smd: 1(-0.65,0.5) 2(-0.65,0) 3(-0.65,-0.5)
  rect 0.991x0.203 smd: 4(0.45,-0.5) 5(0.45,0) 6(0.45,0.5)
VSSOP8_19-68_85X95
  rect 0.813x0.305 smd: 1(-1.55,0.75) 2(-1.55,0.25) 3(-1.55,-0.25) 4(-1.55,-0.75) 5(1.55,-0.75) 6(1.55,-0.25) 7(1.55,0.25) 8(1.55,0.75)
VSSOP8_19-68_85X95_0-9
  rect 0.838x0.305 smd: 1(-1.55,0.75) 2(-1.55,0.25) 3(-1.55,-0.25) 4(-1.55,-0.75) 5(1.55,-0.75) 6(1.55,-0.25) 7(1.55,0.25) 8(1.55,0.75)
VSSOP8_19-68_85X95_0-9#2
  rect 0.838x0.305 smd: 1(-1.55,0.75) 2(-1.55,0.25) 3(-1.55,-0.25) 4(-1.55,-0.75) 5(1.55,-0.75) 6(1.55,-0.25) 7(1.55,0.25) 8(1.55,0.75)
WFQFN24_CDCE6214-Q1_160X160_0-9
  rect 0.61x0.254 smd: 1(-1.9,1.25) 2(-1.9,0.75) 3(-1.9,0.25) 4(-1.9,-0.25) 5(-1.9,-0.75) 6(-1.9,-1.25) 13(1.9,-1.25) 14(1.9,-0.75) 15(1.9,-0.25) 16(1.9,0.25) 17(1.9,0.75) 18(1.9,1.25)
  rect 0.254x0.61 smd: 7(-1.25,-1.9) 8(-0.75,-1.9) 9(-0.25,-1.9) 10(0.25,-1.9) 11(0.75,-1.9) 12(1.25,-1.9) 19(1.25,1.9) 20(0.75,1.9) 21(0.25,1.9) 22(-0.25,1.9) 23(-0.75,1.9) 24(-1.25,1.9)
  rect 2.794x2.794 smd: 25(0,0)
  rect 0.254x0.254 smd: A1(-1.75,1.75) A2(-1.75,-1.75) A3(1.75,-1.75) A4(1.75,1.75)
WQFN24_19-68_160X160
  rect 0.813x0.305 smd: 1(-2,1.25) 2(-2,0.75) 3(-2,0.25) 4(-2,-0.25) 5(-2,-0.75) 6(-2,-1.25) 13(2,-1.25) 14(2,-0.75) 15(2,-0.25) 16(2,0.25) 17(2,0.75) 18(2,1.25)
  rect 0.305x0.813 smd: 7(-1.25,-2) 8(-0.75,-2) 9(-0.25,-2) 10(0.25,-2) 11(0.75,-2) 12(1.25,-2) 19(1.25,2) 20(0.75,2) 21(0.25,2) 22(-0.25,2) 23(-0.75,2) 24(-1.25,2)
  rect 2.692x2.692 smd: 25(0,0)
WSON6_CSD13202Q2_80X80_0-8
  rect 0.457x0.305 smd: 1(-0.975,0.65) 2(-0.975,0) 3(-0.975,-0.65) 4(0.975,-0.65) 5(0.975,0) 6(0.975,0.65)
  rect 0.762x0.305 smd: 7(0.095,-0.65)
  rect 0.991x0.94 smd: 8(0,0.325)
X2SON3_ESD122DMX_30X40_0-4
  rect 0.203x0.203 smd: 1(-0.15,0) 2(0.15,-0.34) 3(0.15,0.34)
X2SON5_TLV7021_30X30_0-4
  custom 0.08x0.08 smd: 1(-0.39,0.24) 2(-0.39,-0.24) 4(0.39,-0.24) 5(0.39,0.24)
  rect 0.356x0.356 smd rot 45: 3(0,0)
X2SON8_15-74_70X50
  rect 0.838x0.203 smd: 1(-0.55,0.6) 2(-0.55,0.2) 3(-0.55,-0.2) 4(-0.55,-0.6) 5(0.55,-0.6) 6(0.55,-0.2) 7(0.55,0.2) 8(0.55,0.6)
X2SON8_TXS0102_40X60_0-4
  rect 0.61x0.178 smd: 1(-0.4,0.525)
  rect 0.508x0.178 smd: 2(-0.45,0.175) 3(-0.45,-0.175) 4(-0.45,-0.525) 5(0.45,-0.525) 6(0.45,-0.175) 7(0.45,0.175) 8(0.45,0.525)
XTAL4_ABM3B_210X130_SMD
  rect 1.803x1.219 smd: 1(-2,-1.2) 2(2,-1.2) 3(2,1.2) 4(-2,1.2)
XTAL4_ABMM_280X200_SMD_1-3
  rect 2.21x1.397 smd: 1(-3.15,-1.27) 2(-3.15,1.27) 3(3.15,1.27)
  rect 2.388x1.397 smd: 4(3.05,-1.27)
XTAL4_XRCGB-FM_80X60_SMD_0-7
  rect 0.762x0.711 smd: 1(-0.675,-0.5) 2(0.675,-0.5) 3(0.675,0.5) 4(-0.675,0.5)
XTAL_ABM3_205X130_SMD_1-4
  rect 1.803x2.413 smd: 1(-1.9,0) 2(1.9,0)
XTAL_ECS-32_130X60_SMD_0-9
  rect 1.118x1.905 smd: 1(-1.25,0) 2(1.25,0)

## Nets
AVDD_3V3_DAC: C29.1 C30.1 C31.1 C32.1 C349.1 C350.1 C351.1 C352.1 FL1.2 R28.2 R29.1 R33.1 R35.2 U5.23(AVDD) U6.23(AVDD) U76.23(AVDD) U77.23(AVDD)
DGND: C1.2 C2.2 C3.2 C11.1 C13.1 C15.1 C17.1 C20.1 C21.1 C22.1 C23.1 C28.2 C29.2 C30.2 C31.2 C32.2 C33.1 C35.2 C37.2 C38.2 C42.2 C43.2 C45.2 C46.2 C47.2 C48.2 C49.2 C50.2 C51.2 C52.2 C53.1 C54.2 C55.2 C56.2 C57.2 C60.1 C61.2 C62.2 C63.2 C64.2 C65.2 C66.2 C67.2 C68.2 C69.2 C70.2 C71.2 C72.2 C73.2 C74.2 C75.2 C76.2 C77.2 C78.2 C81.2 C82.2 C84.2 C85.2 C86.2 C87.2 C88.1 C89.2 C90.2 C92.1 C93.1 C95.2 C96.2 C97.1 C98.2 C99.2 C100.2 C101.2 C102.1 C103.1 C104.1 C105.2 C107.2 C109.2 C121.2 C122.1 C126.1 C128.2 C129.2 C130.2 C133.2 C134.2 C135.2 C136.2 C137.2 C138.2 C140.2 C141.2 C142.2 C146.2 C147.2 C148.2 C149.1 C150.1 C151.1 C160.2 C161.2 C164.2 C165.1 C167.2 C168.2 C169.2 C170.2 C171.2 C172.2 C174.2 C175.2 C176.2 C182.1 C188.1 C190.2 C192.2 C197.2 C201.2 C202.2 C203.1 C205.1 C207.2 C208.2 C209.1 C213.1 C215.1 C216.1 C217.1 C221.2 C222.2 C223.1 C224.2 C225.1 C226.2 C227.2 C228.2 C229.2 C231.1 C232.2 C233.2 C234.2 C235.1 C236.1 C240.2 C241.2 C242.2 C244.2 C245.2 C246.2 C247.1 C248.2 C249.2 C250.2 C251.1 C254.2 C255.2 C256.2 C257.2 C258.2 C259.2 C260.2 C261.2 C262.1 C263.2 C264.1 C265.2 C266.1 C267.2 C269.2 C270.2 C271.2 C272.2 C273.2 C274.2 C275.1 C276.2 C277.2 C278.2 C279.2 C280.1 C281.1 C282.1 C283.1 C284.1 C285.2 C286.1 C287.1 C288.1 C289.1 C290.2 C291.1 C292.2 C293.2 C295.2 C300.1 C301.2 C302.2 C303.2 C305.2 C306.2 C307.2 C308.2 C309.2 C310.2 C312.2 C319.1 C320.1 C321.2 C322.2 C323.2 C324.2 C325.2 C326.2 C327.2 C329.2 C330.2 C332.1 C334.1 C336.1 C338.1 C340.2 C341.1 C342.1 C343.1 C344.1 C349.2 C350.2 C351.2 C352.2 C353.2 C354.2 C355.2 C356.2 C357.2 C358.2 C359.2 C360.2 C361.2 C362.2 C363.2 C364.2 C365.2 C366.2 C367.2 C368.2 C369.2 C370.2 C371.2 C372.2 C373.2 C374.2 C378.2 C379.2 C382.2 C383.2 C384.2 C385.2 C386.2 C387.2 C388.2 C389.2 C390.2 C391.1 C393.1 C394.1 C395.2 C408.2 C409.1 C414.1 C415.1 C416.1 C417.2 C421.1 C427.2 C429.2 C430.1 C432.2 C434.2 C437.2 C440.2 C441.2 C443.2 C445.2 C446.2 C447.2 C448.2 C449.1 C451.2 C453.2 C454.2 C455.1 C460.2 C461.2 C462.2 C463.2 C465.2 C466.2 C467.2 C468.2 C469.1 C470.1 C471.2 C473.1 C477.2 C478.1 C483.2 C484.2 C485.2 C488.2 C489.1 C490.2 C493.2 C494.2 C495.2 C497.2 C498.2 C500.1 C501.2 C502.2 C503.2 C504.2 C505.2 C506.2 C508.2 C509.2 C511.1 C512.2 C514.2 C515.1 C516.1 C517.2 C518.2 C520.2 C521.2 C525.2 C527.2 C528.1 C529.1 C532.2 C533.2 C534.2 C535.2 C536.2 C537.2 C538.2 C546.2 C547.2 C555.2 C560.2 C561.2 C565.2 C572.2 C574.1 C575.1 C576.2 C592.2 C593.2 C598.2 C599.1 C602.2 C604.2 C605.1 C606.1 C607.1 C608.1 C609.1 C610.2 C611.2 C612.1 C613.1 C614.2 C616.2 C617.1 C618.1 C620.2 C622.1 C631.2 C641.2 C642.2 C643.2 C644.2 C646.2 C647.2 C648.2 C649.2 C650.2 C651.2 C652.2 C653.2 C654.2 C655.2 C657.2 C658.2 C659.2 C660.2 C662.2 C663.2 C787.2 C3497.2 C3625.2 C3627.1 C3628.2 C3629.2 C3630.2 C3631.2 C3636.2 C3637.2 C3638.2 C3642.2 C3643.2 C3644.1 C3645.2 C3647.2 C3649.2 C3652.2 C3653.2 C3655.2 C3656.2 C3657.1 C3658.2 C3659.2 C3660.2 C3661.2 C3692.1 C3694.2 C3695.1 C3696.2 C3697.1 C3698.2 C3701.2 C3702.2 C3703.2 C3704.1 C3705.2 C3706.1 C3707.2 C3708.2 C3709.2 C3710.2 C3711.2 C3712.2 C3713.2 C3714.2 C3715.2 C3716.2 C3717.2 C3718.2 C3719.2 C3720.1 C3721.1 C3724.1 C3725.1 C3726.1 C3727.1 C3728.1 C3729.1 C3730.1 C3731.2 C3732.1 C3733.2 C3738.2 C3740.1 C3741.1 C3744.2 C3745.1 C3746.1 C3747.2 C3750.1 C3751.2 C3752.2 C3753.2 C3754.2 C3755.2 C3756.2 C3757.2 C3758.2 C3759.2 C3760.2 C3762.2 C3764.2 C3767.2 C3768.1 C3769.1 C3771.1 C3772.1 C3773.2 C3774.1 D1.1 D2.1(A) D3.1 D6.1(A) D7.2(ANODE) D8.2(ANODE) D9.1(GND) D11.1 D12.1 D13.1 D14.1 D16.2(ANODE) D17.2(ANODE) D18.1 J1.1A J1.1B J2.1A J2.1B J3.1A J3.1B J4.1A J4.1B J7.2 J9.2 J12.7 J12.8 J12.15 J12.16 J12.22 J12.25 J12.26 J12.31 J12.35 J12.36 J12.45 J12.46 J12.49 J12.50 J12.57 J12.58 J12.65 J12.66 J12.75 J12.76 J12.81(GND1) J12.82(GND2) J12.83(GND3) J12.84(GND4) J12.85(GND5) J12.86(GND6) J12.87(GND7) J12.88(GND8) J13.7 J13.8 J13.15 J13.16 J13.22 J13.25 J13.26 J13.31 J13.35 J13.36 J13.45 J13.46 J13.49 J13.50 J13.57 J13.58 J13.65 J13.66 J13.75 J13.76 J13.81(GND1) J13.82(GND2) J13.83(GND3) J13.84(GND4) J13.85(GND5) J13.86(GND6) J13.87(GND7) J13.88(GND8) J14.10 J14.12 J14.16 J14.20 J16.2 J17.5(GND) J18.1 J18.5 J18.8 J18.15 J18.16 J18.17 J18.18 J18.21 J18.24 J18.31 J18.32 J18.33 J18.34 J18.41 J19.1 J19.5 J19.8 J19.15 J19.16 J19.17 J19.18 J19.21 J19.24 J19.31 J19.32 J19.33 J19.34 J19.41 J21.2 J21.10 J22.5(GND) J24.A1(GND#A1) J24.A12(GND#A12) J24.B1(GND#B1) J24.B12(GND#B12) J25.A1(GND#A1) J25.A12(GND#A12) J25.B1(GND#B1) J25.B12(GND#B12) J26.6(VSS) J26.SH1 J26.SH2 J26.SH3 J26.SH4 J31.12 J32.2 J33.2 J34.2 LD3.1(CATHODE) LD5.1(CATHODE) LD6.1(CATHODE) LD9.1(CATHODE) LD13.1(CATHODE) Q1.4(S1) Q1.7(S2) Q2.2(EMITTER) Q3.2(S) Q5.4(S1) Q5.7(S2) Q7.3(D) Q10.4(S1) Q10.7(S2) Q12.3(D) R22.2 R26.2 R27.2 R30.2 R31.2 R32.2 R36.1 R37.1 R61.2 R63.2 R68.1 R76.2 R85.2 R94.2 R107.2 R112.1 R143.2 R145.2 R146.2 R147.2 R148.2 R149.2 R150.2 R151.2 R152.2 R153.2 R154.2 R155.2 R156.2 R157.2 R158.2 R159.2 R160.2 R202.2 R203.1 R214.1 R217.1 R218.2 R229.1 R230.1 R231.1 R232.1 R238.2 R254.1 R258.2 R278.1 R289.2 R303.2 R313.2 R320.2 R341.1 R355.1 R367.2 R373.2 R381.2 R385.1 R403.2 R404.2 R415.1 R418.1 R422.1 R429.2 R430.2 R438.1 R442.1 R451.2 R456.2 R489.1 R490.1 R504.2 R531.1 R545.2 R553.2 R555.1 R556.2 R560.2 R561.2 R562.2 R564.2 R569.1 R591.1 R606.2 R607.2 R609.1 R610.1 R613.1 R618.1 R622.1 R623.1 R624.1 R626.1 R628.1 R632.2 R635.1 R639.1 R642.1 R662.2 R672.2 R681.2 R682.2 R3651.2 R3652.2 R3724.2 R3727.1 R3736.2 R5216.1 R5681.2 R5709.2 R5728.2 R5733.2 R5745.1 R5754.1 R5760.1 R5766.2 R5767.2 R5773.2 R5789.2 R5799.1 R5800.1 R5806.2 R5820.1 R5821.1 R5822.2 R5823.1 R5829.1 SW5.1 SW5.4 SW6.1 SW6.4 SW7.1 SW7.4 SW8.1 SW8.4 SW10.1 SW10.4 TP1.1(TP) TP2.1(TP) TP40.1(TP) TP41.1(TP) TP42.1(TP) TP44.1(TP) TP77.1(TP) TP85.1(TP) TP106.1(TP) U2.2(GND) U4.2(GND) U5.25(EP_PAD) U5.A1(VSS#A1) U5.A2(VSS#A2) U5.A3(VSS#A3) U5.A4(VSS#A4) U6.25(EP_PAD) U6.A1(VSS#A1) U6.A2(VSS#A2) U6.A3(VSS#A3) U6.A4(VSS#A4) U7.8(AVSS) U7.33(VSS) U8.8(AVSS) U8.33(VSS) U10.5(GND) U11.2(GND) U12.4(GND) U14.3(GND) U15.25(EP) U15.A1(GND#A1) U15.A2(GND#A2) U15.A3(GND#A3) U15.A4(GND#A4) U18.9(GND) U18.25(PAD) U21.25(GND) U21.33(EP) U23.3(GND) U25.4(GND) U26.3(GND) U27.3(GND) U28.B3(VSS) U28.C1(VSSQ#C1) U28.E5(VSSQ#E5) U29.5(GND) U39.4(GND) U40.7(GND) U41.1(ANODE) U43.2(GND) U46.2(GND) U48.10(GNDA) U48.17(GND#17) U48.48(GND#48) U48.55(GND#55) U48.58(GND#58) U48.64(W\A\K\E\) U48.66(XOSC0) U48.80(GND#80) U48.114(GND#114) U49.A6(VSS#A6) U49.C4(VSSQ#C4) U49.E7(VSS#E7) U49.G5(VSS#G5) U49.H10(VSS#H10) U49.J5(VSS#J5) U49.K8(VSS#K8) U49.N2(VSSQ#N2) U49.N5(VSSQ#N5) U49.P4(VSSQ#P4) U49.P6(VSSQ#P6) U51.4(GND) U54.2(GND) U55.6(GND) U55.9(PAD) U56.5(AGND) U56.14(PGND_B34) U56.32(PGND_B12) U57.43(GND) U59.4(GND) U59.9(EP) U60.3(GND) U61.5(VSS) U62.2(GND) U64.1(GND1) U64.5(GND2) U64.10(AGND) U64.11(GND3) U64.13(TEST) U64.15(GND4) U64.25(GND5) U64.35(GND6) U64.47(GND7) U64.51(GND8) U65.4(GND) U66.3(GND) U66.7(EP) U67.4(GND) U68.2(GND) U69.4(GND) U71.3(GND) U73.4(GND) U73.7(EP) U75.3(GND) U76.25(EP_PAD) U76.A1(VSS#A1) U76.A2(VSS#A2) U76.A3(VSS#A3) U76.A4(VSS#A4) U77.25(EP_PAD) U77.A1(VSS#A1) U77.A2(VSS#A2) U77.A3(VSS#A3) U77.A4(VSS#A4) U81.11(GND1) U81.12(GND2) U81.13(GND3) U81.25(EP) U82.25(GND) U82.33(EP) U83.11(GND1) U83.12(GND2) U83.13(GND3) U83.25(EP) U86.2(GND) U87.3(GND) U88.3(GND) U90.3(A2) U90.5(GND) U90.6(B2) U91.7(GND) U92.C1(GND) U93.3(GND) U97.10(GND1) U97.11(GND2) U98.4(GND) U102.4(GND) U107.4(GND) U109.3(A2) U109.5(GND) U109.6(B2) U110.10(GND1) U110.11(GND2) U113.B3(A0) U113.C1(GND) U113.C3(A1) U114.1(A1) U114.2(A0) U114.7(GND) U115.C1(GND) U115.C3(A1) U116.1(A1) U116.7(GND) U117.1(1\O\E\) U117.10(GND1) U117.11(GND2) U117.16(2\O\E\) U118.7(GND) U119.C1(GND) U120.2(GND) U123.C1(GND) U124.7(GND) U125.1(1\O\E\) U125.7(1A2) U125.9(2A2) U125.10(GND1) U125.11(GND2) U125.12(2B2) U125.14(1B2) U125.16(2\O\E\) U126.1(1\O\E\) U126.7(1A2) U126.9(2A2) U126.10(GND1) U126.11(GND2) U126.12(2B2) U126.14(1B2) U126.16(2\O\E\) U127.4(GND) U129.20(GND#20) U129.51(GND#51) U129.59(GND#59) U132.1(GND#1) U132.2(GND#2) U132.3(GND#3) U132.7(GND#7) U133.1(GND#1) U133.2(GND#2) U133.3(GND#3) U133.7(GND#7) U134.3(AGND) U134.9(PGND1) U134.11(PGND2) U135.3(GND) U135.7(EP) U136.A1(VSS#A1) U136.A19(VSS#A19) U136.B2(VSS#B2) U136.C3(VSS#C3) U136.C19(VSS#C19) U136.D1(VSS#D1) U136.D3(VSS#D3) U136.D4(VSS#D4) U136.D8(VSS#D8) U136.D11(VSS#D11) U136.D14(VSS#D14) U136.D19(VSS#D19) U136.E5(VSS#E5) U136.E9(VSS#E9) U136.E10(VSS#E10) U136.E11(VSS#E11) U136.E12(VSS#E12) U136.E14(VSS#E14) U136.E15(VSS#E15) U136.E17(VSS#E17) U136.E18(VSS#E18) U136.F4(VSS#F4) U136.F10(VSS#F10) U136.F11(VSS#F11) U136.F14(VSS#F14) U136.F15(VSS#F15) U136.F16(VSS#F16) U136.G4(VSS#G4) U136.G6(VSS#G6) U136.G8(VSS#G8) U136.G9(VSS#G9) U136.G12(VSS#G12) U136.G13(VSS#G13) U136.G15(VSS#G15) U136.H3(VSS#H3) U136.H6(VSS#H6) U136.H11(VSS#H11) U136.J7(VSS#J7) U136.J11(VSS#J11) U136.J13(VSS#J13) U136.J15(VSS#J15) U136.K8(VSS#K8) U136.K11(VSS#K11) U136.K12(VSS#K12) U136.K15(VSS#K15) U136.L5(VSS#L5) U136.L7(VSS#L7) U136.L9(VSS#L9) U136.L10(VSS#L10) U136.L13(VSS#L13) U136.L14(VSS#L14) U136.L15(VSS#L15) U136.M5(VSS#M5) U136.M8(VSS#M8) U136.M12(VSS#M12) U136.M15(VSS#M15) U136.N5(VSS#N5) U136.N6(VSS#N6) U136.N7(VSS#N7) U136.N9(VSS#N9) U136.N13(VSS#N13) U136.N14(VSS#N14) U136.N15(VSS#N15) U136.P5(VSS#P5) U136.P6(VSS#P6) U136.P14(VSS#P14) U136.P15(VSS#P15) U136.R5(VSS#R5) U136.R6(VSS#R6) U136.R7(VSS#R7) U136.R10(VSS#R10) U136.R12(VSS#R12) U136.R13(VSS#R13) U136.R14(VSS#R14) U136.R15(VSS#R15) U136.T5(VSS#T5) U136.T8(VSS#T8) U136.T9(VSS#T9) U136.T10(VSS#T10) U136.T16(VSS#T16) U136.U4(VSS#U4) U136.U5(VSS#U5) U136.U8(VSS#U8) U136.U10(VSS#U10) U136.U17(VSS#U17) U136.V4(VSS#V4) U136.V10(VSS#V10) U136.V18(VSS#V18) U136.W1(VSS#W1) U136.W3(VSS#W3) U136.W6(VSS#W6) U136.W10(VSS#W10) U136.W19(VSS#W19) U140.B3(VSS) U140.C1(VSSQ#C1) U140.E5(VSSQ#E5) U2345.11(GND) U2346.3(GND) U2347.4(GND) U2348.3(GND) U2349.3(GND#3) U2349.8(GND#8) U2350.3(GND#3) U2350.8(GND#8) U2351.3(GND) U2352.3(GND) U2353.1(1\O\E\) U2353.7(1A2) U2353.9(2A2) U2353.10(GND1) U2353.11(GND2) U2353.12(2B2) U2353.14(1B2) U2353.16(2\O\E\) U2355.3(GND) U2356.3(GND) U2357.5(GND) U2358.4(GND) U3068.2(GND) U3070.3(GND) U3072.8(GND1) U3072.19(GND2) U3072.38(GND4) U3072.49(GND3) U3076.2(GND) U3077.7(GND) U3078.1(A1) U3078.7(GND) U3079.1(A1) U3079.7(GND) U3080.C1(GND) U3080.C3(A1) U3081.C1(GND) U3081.C3(A1) U3083.3(A2) U3083.5(GND) U3083.6(B2) U3084.4(GND) U3086.3(GND) U3087.3(GND) Y1.2 Y1.4 Y3.2 Y3.4 Y5.2 Y5.4 Y8.2 Y8.4
DVDD1V8_ALERT: R305.1 U123.A3(ALERT) U124.3(ALERT)
DVDD3V3_ALERT: R505.1 U91.3(ALERT) U92.A3(ALERT)
DVDD3V3_N: R327.4 R539.2
DVDD3V3_P: R327.1 R540.2
VBAT_IN: C49.1 C55.1 C95.1 C100.1 J7.1 U7.21(VBAT_IN) U8.21(VBAT_IN)
VBUS_TYPEC1: C321.1 C326.1 C327.1 C641.1 C643.1 C654.1 C655.1 D5.1(A1) J24.A4(VBUS1) J24.A9(VBUS2) J24.B4(VBUS3) J24.B9(VBUS4) R3933.1 TP107.1(TP) U129.13(VBUS1) U133.4(IN1) U133.5(IN2) U133.6(IN3)
VBUS_TYPEC2: C325.1 C638.1 C642.1 C644.1 C646.1 C647.1 C649.1 C650.1 C652.1 C653.1 D5.2(A2) J25.A4(VBUS1) J25.A9(VBUS2) J25.B4(VBUS3) J25.B9(VBUS4) Q8.4(D1) Q8.7(D2) R401.2 R402.1 R675.1 TP108.1(TP) U129.3(VBUS2) U132.4(IN1) U132.5(IN2) U132.6(IN3)
VCC1V8_CLKBUF: C265.1 C266.2 C284.2 C286.2 FL10.1 R329.2 R348.2 U62.4(VDD) U65.6(VDD)
VCC1V8_SYS: C37.1 C72.1 C73.1 C75.1 C76.1 C101.1 C102.2 C126.2 C137.1 C138.1 C141.1 C142.1 C146.1 C148.1 C149.2 C151.2 C160.1 C161.1 C164.1 C167.1 C168.1 C242.1 C256.1 C257.1 C261.1 C371.1 C372.1 C373.1 C374.1 C388.1 C389.1 C390.1 C395.1 C408.1 C414.2 C421.2 C455.2 C470.2 C478.2 C503.1 C511.2 C514.1 C518.1 C528.2 C555.1 C593.1 C608.2 C617.2 C3701.1 C3703.1 C3704.2 C3705.1 C3706.2 C3707.1 C3708.1 C3709.1 C3718.1 C3719.1 C3721.2 C3725.2 C3726.2 C3728.2 C3729.2 C3733.1 C3769.2 C3773.1 C3774.2 J12.10 J12.12 J13.10 J13.12 J29.1 L6.2 R17.2 R18.2 R67.2 R69.1 R70.2 R75.1 R83.1 R97.2 R115.1 R117.1 R122.2 R123.2 R124.2 R166.1 R220.1 R225.1 R242.1 R259.1 R262.1 R263.1 R264.1 R266.1 R267.1 R268.1 R269.1 R270.1 R275.1 R288.1 R291.1 R301.1 R334.2 R361.1 R375.1 R419.2 R423.2 R443.2 R444.2 R445.2 R446.2 R447.2 R448.2 R449.2 R450.2 R452.2 R454.2 R464.1 R465.1 R480.1 R533.2 R534.2 R536.2 R550.1 R554.2 R559.1 R565.1 R575.1 R598.1 R603.1 R611.1 R612.1 R614.2 R615.1 R631.1 R636.2 R684.1 R685.1 R5213.2 R5684.2 R5693.2 R5698.2 R5699.2 R5710.2 R5711.2 R5712.2 R5713.2 R5714.2 R5715.2 R5716.2 R5717.2 R5744.2 R5746.2 R5753.2 R5761.1 R5795.1 R5796.1 R5797.1 R5798.1 R5808.2 R5810.2 U2.5(VCC) U5.6(IOVDD) U6.6(IOVDD) U11.3(VCCA) U12.1(VCC) U21.27(VCCP) U21.31(VCC) U26.5(VCC) U27.5(VCC) U28.B4(VCC) U28.D1(VCCQ#D1) U28.E4(VCCQ#E4) U29.8(VCCB) U39.1(VCCA) U43.5(VCC) U49.C6(VCCQ#C6) U49.M4(VCCQ#M4) U49.N4(VCCQ#N4) U49.P3(VCCQ#P3) U49.P5(VCCQ#P5) U56.18(VIO) U56.26(PVIN_LDO3) U76.6(IOVDD) U77.6(IOVDD) U81.23(VCCB1) U81.24(VCCB2) U83.23(VCCB1) U83.24(VCCB2) U86.5(VCC) U90.1(VCCA) U93.5(VCC) U97.3(VCCA) U98.8(VCC) U102.1(VCCA) U109.1(VCCA) U110.3(VCCA) U125.3(VCCA) U126.3(VCCA) U140.B4(VCC) U140.D1(VCCQ#D1) U140.E4(VCCQ#E4) U2345.2(VCCA) U2346.8(VDD) U2347.8(V+) U2348.5(VCC) U2351.8(VDD) U2352.8(VDD) U2353.3(VCCA) U2355.5(VCC) U2358.8(VCC) U3077.1(VCCA) U3083.1(VCCA) U3086.5(VCC) U3087.5(VCC)
VCC1V8_SYS_N: R334.4 R335.2
VCC1V8_SYS_P: R331.2 R334.1
VCC1V8_SYS_SW: L6.1 U56.13(SW_B3)
VCC1V8_TA: C136.1 C236.2 C391.2 C393.2 C394.2 C409.2 C529.2 R126.2 R127.2 R128.2 R129.2 R130.2 R131.2 R132.2 R133.2 R134.2 R135.2 R136.2 R137.2 R138.2 R139.2 R140.2 R141.2 R277.2 R285.1 R439.2 R457.2 R461.2 R507.1 R511.1 R513.1 R516.1 R524.1 R526.1 R578.1 R582.1 R583.1 R643.2 U23.5(VCC) U51.1(VCCA) U81.1(VCCA) U82.27(VCCP) U82.31(VCC) U83.1(VCCA) U107.1(VCCA)
VCC2V5_PG: R637.1 U127.2(PG)
VCC3V3_XDS: C147.1 C192.1 C208.1 C221.1 C222.1 C231.2 C232.1 C234.1 C235.2 C241.1 C243.1 C430.2 C469.2 C473.2 C488.1 C500.2 C515.2 C3720.2 R118.1 R119.1 R236.1 R237.1 R241.1 R246.2 R280.1 R306.1 R510.1 R512.1 R515.1 R517.1 R519.1 R520.2 R521.2 R522.2 R523.2 R525.1 R549.2 R551.1 R552.1 TP68.1(TP) U25.8(VCCB) U40.14(VCC) U48.7(VDD#7) U48.8(VDDA) U48.16(VDD#16) U48.26(VDD#26) U48.28(VDD#28) U48.39(VDD#39) U48.47(VDD#47) U48.51(VDD#51) U48.52(VDD#52) U48.69(VDD#69) U48.79(VDD#79) U48.90(VDD#90) U48.101(VDD#101) U48.113(VDD#113) U48.122(VDD#122) U51.8(VCCB) U55.3(OUT1) U55.4(OUT2) U97.2(VCCB) U102.8(VCCB) U107.8(VCCB) U109.8(VCCB) U2353.2(VCCB)
VCC_0V85: C3738.1 R5747.1 U56.25(VOUT_LDO3)
VCC_1V8_FT4232: C263.1 C280.2 C281.2 C599.2 U64.12(VCORE#12) U64.37(VCORE#37) U64.49(VREGOUT) U64.64(VCORE#64)
VCC_1V8_IOVDD: C71.1 C74.1 C84.1 C85.1 C109.1 C340.1 R20.1 R23.1 R60.1 R62.1 R67.1 R78.2 R90.2 R413.2 R416.2 U7.27(IOVDD) U8.27(IOVDD) U14.5(VCC) U75.5(VCC)
VCC_3V3_AVDD: C52.1 C53.2 C63.1 C68.1 C86.1 C90.1 C97.2 C98.1 FL2.2 L2.1 L3.1 U7.1(AVDD) U7.3(BSTVDD) U8.1(AVDD) U8.3(BSTVDD)
VCC_3V3_FT4232: C262.2 C264.2 C275.2 C285.1 C288.2 C289.2 C575.2 C612.2 C618.2 FL17.2 FL18.2 LD7.2(ANODE) R321.2 R328.2 R333.2 U61.8(VCC) U64.20(VCCIO#20) U64.31(VCCIO#31) U64.42(VCCIO#42) U64.50(VREGIN) U64.56(VCCIO#56) U66.1(OUT) U117.2(VCCB) U125.2(VCCB) U126.2(VCCB)
VCC_3V3_SYS: C28.1 C33.2 C99.1 C122.2 C140.1 C150.2 C165.2 C169.1 C258.1 C259.1 C260.1 C271.1 C274.1 C277.1 C279.1 C293.1 C415.2 C416.2 C427.1 C498.1 C504.1 C520.1 C525.1 C560.1 C592.1 C598.1 C602.1 C604.1 C787.1 C3659.1 C3660.1 C3698.1 C3724.2 C3727.2 C3730.2 C3732.2 C3762.1 C3764.1 C3768.2 FL1.1 FL2.1 FL23.2 J14.5 J18.44 J18.46 J19.44 J19.46 J29.3 L7.2 R56.1 R58.1 R98.2 R180.2 R211.1 R212.1 R260.2 R292.2 R324.2 R327.2 R342.1 R343.2 R344.1 R347.1 R351.2 R356.1 R360.1 R362.2 R363.2 R440.2 R482.1 R485.2 R597.2 R601.2 R602.2 R616.2 R620.2 R625.2 R629.2 R630.2 R638.2 R641.2 R645.1 R5215.1 R5687.2 R5688.2 R5735.2 R5741.1 R5742.1 R5759.2 R5764.2 R5777.1 R5824.1 R5825.1 U4.1(VIN) U11.7(VCCB) U18.21(VCCP) U18.23(VCCI) U25.1(VCCA) U29.1(VCCA) U39.8(VCCB) U49.E6(VCC#E6) U49.F5(VCC#F5) U49.J10(VCC#J10) U49.K9(VCC#K9) U57.1(VCC#1) U57.17(VCC#17) U57.30(VCC#30) U68.5(VCC) U87.5(VCC) U88.5(VCC) U90.8(VCCB) U91.1(A1) U91.6(VS) U92.B1(VS) U92.C3(A1) U110.2(VCCB) U113.B1(VS) U114.6(VS) U115.B1(VS) U115.B3(A0) U116.2(A0) U116.6(VS) U118.2(A0) U118.6(VS) U119.B1(VS) U119.B3(A0) U120.5(VCC) U123.B1(VS) U123.B3(A0) U123.C3(A1) U124.1(A1) U124.2(A0) U124.6(VS) U2357.1(V+) U3072.17(VCC) U3077.14(VCCB) U3078.6(VS) U3079.6(VS) U3080.B1(VS) U3081.B1(VS) U3083.8(VCCB)
VCC_3V3_SYS_CLK_BUF: C3771.2 C3772.2 FL23.1 R5790.1 U3084.6(VDD)
VCC_3V3_SYS_REG_SW: L7.1 U56.15(SW_B4)
VCC_5V0: C128.1 C129.1 C130.1 C133.1 C134.1 C135.1 C170.1 C171.1 C172.1 C174.1 C175.1 C176.1 C197.1 C255.1 C317.1 C318.1 C546.1 C547.1 C561.1 C565.1 C572.1 C576.1 C620.1 C639.1 C3497.1 C3636.1 C3637.1 C3638.1 C3643.1 C3692.2 C3695.2 C3747.1 J12.2 J12.4 J12.6 J13.2 J13.4 J13.6 L24.2 Q9.4(D1) Q9.7(D2) R240.1 R543.1 R665.1 R676.1 R3661.1 R3720.1 R3725.1 R5774.1 TP103.1(TP) U46.1(IN) U56.3(VCCA) U56.12(PVIN_B3) U56.16(PVIN_B4) U56.20(PVIN_LDO12) U56.30(PVIN_B2) U56.34(PVIN_B1) U59.8(IN) U127.6(VIN) U134.1(BIAS) U135.6(IN) U3068.3(VCC) U3076.1(IN)
VCC_5V0_PG: R3653.1 U54.3(B) U86.3(B) U134.5(PGOOD)
VCC_CORE: C226.1 C227.1 C228.1 C229.1 C532.1 C533.1 C534.1 C535.1 C536.1 C537.1 L4.2 L5.2 R265.4 R5748.1
VCC_CORE_N: R265.2 R572.2
VCC_CORE_P: R265.3 R571.2
VDD_0V85_N: R581.1 R585.2
VDD_0V85_P: R581.4 R584.2
VDD_1V8_N: R311.2 R316.4
VDD_1V8_P: R310.2 R316.1
VDD_2V5: C272.1 C273.1 C276.1 C278.1 C614.1 C615.1 C616.1 J18.4 J18.6 J19.4 J19.6 L11.2 R634.1 R637.2 TP92.1(TP)
VDD_CANUART: C207.1 R255.1 R5786.3 U46.5(OUT)
VDD_CANUART_ALERT: R5778.1 U3078.3(ALERT) U3080.A3(ALERT)
VDD_CANUART_N: R5780.2 R5786.1
VDD_CANUART_P: R5781.2 R5786.4
VDD_CORE: C441.1 C445.1 C448.1 C460.1 C462.1 C468.1 C477.1 C494.1 C657.1 C658.1 C659.1 C660.1 C662.1 C663.1 C3661.1 C3751.1 C3752.1 C3753.1 C3754.1 C3755.1 C3756.1 C3757.1 FL8.1 R265.1 R5828.1 TP53.1(TP) U136.G7(VDD_CORE#G7) U136.G11(VDD_CORE#G11) U136.G14(VDD_CORE#G14) U136.H9(VDD_CORE#H9) U136.H10(VDD_CORE#H10) U136.H13(VDD_CORE#H13) U136.J12(VDD_CORE#J12) U136.K7(VDD_CORE#K7) U136.K9(VDD_CORE#K9) U136.K13(VDD_CORE#K13) U136.L8(VDD_CORE#L8) U136.L11(VDD_CORE#L11) U136.L12(VDD_CORE#L12) U136.M7(VDD_CORE#M7) U136.M9(VDD_CORE#M9) U136.M13(VDD_CORE#M13) U136.P7(VDD_CORE#P7) U136.P13(VDD_CORE#P13)
VDD_CORE_ALERT: R586.1 U113.A3(ALERT) U114.3(ALERT)
VDD_CORE_N: C524.2 R572.1 U113.D1(BUS) U113.D2(IN-) U114.8(VBUS) U114.9(IN-)
VDD_CORE_P: C524.1 R571.1 U113.D3(IN+) U114.10(IN+)
VDD_CORE_REG_SW1: L4.1 U56.33(SW_B1)
VDD_CORE_REG_SW2: L5.1 U56.31(SW_B2)
VDD_MMC0: C69.1 FL4.1 U4.5(QOD) U4.6(VOUT)
VDD_MMC0_SD: C88.2 C93.2 FL4.2 J26.4(VDD) TP21.1(TP)
VDDA1V8: C254.1 C290.1 FL10.2 R316.2 U56.19(VOUT_LDO1)
VDDA_1V8: C202.1 C483.1 FL6.1 FL9.1 FL13.1 FL20.1 FL21.1 FL22.1 R316.3 SW11.1 TP79.1(TP)
VDDA_1V8_ALERT: R608.1 U118.3(ALERT) U119.A3(ALERT)
VDDA_1V8_FB1: C463.1 C485.1 C501.1 FL13.2 U136.J9(VDDA_PLL0) U136.J10(VDDA_PLL1) U136.M11(VDDA_PLL2)
VDDA_1V8_FB2: C467.1 C3656.1 FL6.2 U136.K5(VDDA_TEMP0) U136.N11(VDDA_TEMP1)
VDDA_1V8_FB3: C3647.1 FL20.2 U136.H7(VDDA_MCU)
VDDA_1V8_FB4: C3649.1 FL21.2 U136.P10(VDDA_1P8_USB)
VDDA_1V8_FB_OSC: C508.1 FL9.2 U136.F5(VDDS_OSC0)
VDDA_1V8_N: C597.2 R311.1 U118.8(VBUS) U118.9(IN-) U119.D1(BUS) U119.D2(IN-)
VDDA_1V8_P: C597.1 R310.1 U118.10(IN+) U119.D3(IN+)
VDDA_ADC0: C3652.1 FL22.2 U136.J5(VDDA_ADC0)
VDDA_CORE_USB: C495.1 C497.1 C3767.1 FL8.2 U136.N10(VDDA_CORE_USB)
VDDA_SYS_MON: C449.2 R543.2 R545.1 U136.H8(VMON_ER_VSYS)
VDDC_1V2: C233.1 C240.1 C516.2 U48.87(VDDC#87) U48.115(VDDC#115)
VDDIM: C521.1 C527.1 U49.C2(VDDIM)
VDDR_CANUART: C3653.1 R3731.2 U136.E7(VDDR_CANUART)
VDDR_CORE: C447.1 C465.1 C466.1 C490.1 C493.1 C505.1 C3758.1 C3759.1 C3760.1 R272.1 R581.2 TP60.1(TP) U136.G10(VDDR_CORE#G10) U136.H12(VDDR_CORE#H12) U136.J8(VDDR_CORE#J8) U136.K10(VDDR_CORE#K10) U136.M10(VDDR_CORE#M10) U136.M14(VDDR_CORE#M14) U136.N8(VDDR_CORE#N8) U136.N12(VDDR_CORE#N12)
VDDR_CORE_0V85: R581.3 R5747.2 R5748.2
VDDR_CORE_ALERT: R596.1 U115.A3(ALERT) U116.3(ALERT)
VDDR_CORE_N: C559.2 R585.1 U115.D1(BUS) U115.D2(IN-) U116.8(VBUS) U116.9(IN-)
VDDR_CORE_P: C559.1 R584.1 U115.D3(IN+) U116.10(IN+)
VDDSHV_CANUART: C538.1 C574.2 C3644.2 C3694.1 C3696.1 C3731.1 C3740.2 R282.1 R318.2 R322.1 R326.1 R371.1 R590.2 R592.1 R593.1 R643.1 R3653.2 R3723.1 R3726.2 R5638.2 R5692.2 R5736.2 R5737.2 R5756.1 R5787.3 TP80.1(TP) U54.5(VCC) U117.3(VCCA) U135.1(OUT) U2356.8(VDD) U3068.5(VIO) U3070.5(VCC)
VDDSHV_CANUART_ALERT: R5782.1 U3079.3(ALERT) U3081.A3(ALERT)
VDDSHV_CANUART_N: R5784.2 R5787.1
VDDSHV_CANUART_P: R5785.2 R5787.4
VDDSHV_CANUART_PG: C3642.1 R3726.1 U135.5(PG)
VDDSHV_SDIO: C103.2 C201.1 C246.1 R54.2 R55.2 R57.2 R64.2 R65.2 R66.2 R243.1 U10.10(VCC) U56.21(VOUT_LDO2)
VINT_LDO: C249.1 TP74.1(TP) U56.7(VOUT_LDOVINT)
ADC0_AIN0: J31.1 R5720.2 U2349.1(IO1) U2349.10(NC4)
ADC0_AIN0_R: C3710.1 R5720.1 U136.F1(ADC0_AIN0)
ADC0_AIN1: J31.3 R5721.2 U2349.2(IO2) U2349.9(NC3)
ADC0_AIN1_R: C3711.1 R5721.1 U136.H1(ADC0_AIN1)
ADC0_AIN2: J31.5 R5722.2 U2349.4(IO3) U2349.7(NC2)
ADC0_AIN2_R: C3712.1 R5722.1 U136.K2(ADC0_AIN2)
ADC0_AIN3: J31.7 R5723.2 U2349.5(IO4) U2349.6(NC1)
ADC0_AIN3_R: C3713.1 R5723.1 U136.K1(ADC0_AIN3)
ADC0_AIN4: J31.9 R5724.2 U2350.1(IO1) U2350.10(NC4)
ADC0_AIN4_R: C3714.1 R5724.1 U136.F2(ADC0_AIN4)
ADC0_AIN5: J31.11 R5725.2 U2350.2(IO2) U2350.9(NC3)
ADC0_AIN5_R: C3715.1 R5725.1 U136.G2(ADC0_AIN5)
ADC0_AIN6: J31.4 R5726.2 U2350.4(IO3) U2350.7(NC2)
ADC0_AIN6_R: C3716.1 R5726.1 U136.J1(ADC0_AIN6)
ADC0_AIN7: J31.6 R5727.2 U2350.5(IO4) U2350.6(NC1)
ADC0_AIN7_R: C3717.1 R5727.1 U136.J2(ADC0_AIN7)
ADC0_EXT_TRIGGER: J31.8 U136.V2(GPIO1_49)
ADC0_REFN: C3742.2 C3743.1 R5728.1 U136.H2(ADC0_REFN)
ADC0_REFP: C3742.1 C3743.2 SW11.2(COM) U136.G1(ADC0_REFP)
ADC0_REFP_HDR: C3744.1 C3745.2 J31.2 SW11.3
ADCIN1: R679.2 R681.1 U129.6(ADCIN1)
ADCIN2: R678.2 R682.1 U129.10(ADCIN2)
ADDR0_IO_EXP: R107.1 U21.26(ADDR)
ADDR1_IO_EXP: R94.1 U18.18(ADDR)
AEC1_GPIO0_0: J12.42 U136.A6(MCU_GPIO0_15)
AEC1_GPIO0_1: J12.44 R5757.2
AEC1_REFCLK_SEL: R5797.2 U21.23(P26) U2346.1(SEL1)
AEC1_REFCLKIN: J12.33 U2346.2(S1A)
AEC1_REFCLKOUT: J12.47 U2346.9(S1B)
AEC2_GPIO0_0: J13.42 U136.A9(MCU_GPIO0_4)
AEC2_GPIO0_1: J13.44 U136.B8(MCU_GPIO0_3)
AEC2_REFCLK_SEL: R5798.2 U21.24(P27) U2346.5(SEL2)
AEC2_REFCLKIN: J13.33 U2346.4(S2A)
AEC2_REFCLKOUT: J13.47 U2346.7(S2B)
AUDIO_EXT_REFCLK0: R538.2 U2346.10(D1)
AUDIO_EXT_REFCLK1: R506.2 U2346.6(D2)
AUDIO_EXT_REFCLK1__R: R506.1 U136.T1(SPI2_CS3)
AUDIO_EXT_REFCLK2: R5686.1 R5689.1
AUDIO_EXT_REFCLK2_R: R5689.2 U136.V3(GPIO1_72)
AUDIO_EXT_REFCLK2_S0: R5795.2 U21.21(P24) U2347.6(IN1)
AUDIO_EXT_REFCLK2_S1: R5796.2 U21.22(P25) U2347.5(IN2)
BOOTMODE0: RA6.1 U81.14(B8)
BOOTMODE1: RA2.1 U81.15(B7)
BOOTMODE2: RA5.1 U81.16(B6)
BOOTMODE3: RA2.2 U81.17(B5)
BOOTMODE4: RA2.3 U81.18(B4)
BOOTMODE5: RA6.4 U81.19(B3)
BOOTMODE6: RA7.4 U81.20(B2)
BOOTMODE7: RA5.3 U81.21(B1)
BOOTMODE8: RA5.2 U83.14(B8)
BOOTMODE9: RA2.4 U83.15(B7)
BOOTMODE10: RA5.4 U83.16(B6)
BOOTMODE11: RA7.1 U83.17(B5)
BOOTMODE12: RA6.3 U83.18(B4)
BOOTMODE13: RA6.2 U83.19(B3)
BOOTMODE14: RA7.2 U83.20(B2)
BOOTMODE15: RA7.3 U83.21(B1)
BOOTMODE_I2C_EN: R578.2 U107.5(EN)
BOOTMODE_I2C_SCL: R579.1 R583.2 TP71.1(TP) U82.29(SCL)
BOOTMODE_I2C_SDA: R580.1 R582.2 TP45.1(TP) U82.30(SDA)
BOOTMODEON: R112.2 U23.4(Y) U81.22(O\E\) U83.22(O\E\)
BUF_BOOTMODE_I2C0_SCL: R119.2 U25.7(SCLB) U48.82(PL1)
BUF_BOOTMODE_I2C0_SDA: R118.2 U25.6(SDAB) U48.81(PL0)
BUF_BOOTMODE_I2C_SCL: R552.2 U48.49(PG0) U107.7(SCLB)
BUF_BOOTMODE_I2C_SDA: R551.2 U48.50(PG1) U107.6(SDAB)
BUF_TEST_GPIO1: R519.2 U40.1(1A) U48.74(PM4)
BUF_TEST_GPIO2: R280.2 U48.73(PM5) U51.7(B1)
BUF_TEST_GPIO3: R515.2 U40.3(2A) U48.72(PM6)
BUF_TEST_GPIO4: R510.2 U40.5(3A) U48.71(PM7)
BUF_TEST_PORZN: R512.2 U40.9(4A) U48.77(PM1)
BUF_TEST_POWERDOWN: R525.2 U40.13(6A) U48.78(PM0)
BUF_TEST_WARMRESETN: R517.2 U40.11(5A) U48.76(PM2)
CAN-FD_INH: R3028.2 TP585.1(TP) U3068.7(INH)
CAP_VDDS0: C454.1 U136.L6(CAP_VDDS0)
CAP_VDDS1: C434.1 U136.F13(CAP_VDDS1)
CAP_VDDS2: C446.1 U136.R11(CAP_VDDS2)
CAP_VDDS3: C432.1 U136.H15(CAP_VDDS3)
CAP_VDDS5: C443.1 U136.P8(CAP_VDDS5)
CAP_VDDS_CANUART: C509.1 U136.E6(CAP_VDDS_CANUART)
CAP_VDDS_MCU: C484.1 U136.E8(CAP_VDDS_MCU)
CDCE_CLKOUT_1: R89.1 U2347.3(NO2)
CLKOUT0: R336.2 R337.2 U65.1(CLKIN)
CLKOUT_OSC: R336.1 U62.3(OUT)
CORE_CONFIG: R371.2 SW7.3 TP76.1(TP) U56.8(GPIO3)
CPSW_ETH_INTN: R621.1 U3077.12(B2)
CPSW_ETH_INTN_1V8: R205.2 U3077.3(A2)
CPSW_RGMII1_BCLK: J18.48 U29.3(A2)
CPSW_RGMII1_BCLK_1V8: U29.6(B2) U2347.2(NO1)
CPSW_RGMII1_BRD_CONN_DET: J18.36 R355.2
CPSW_RGMII1_COL: J18.14 TP590.1(TP)
CPSW_RGMII1_CRS: J18.30 TP591.1(TP)
CPSW_RGMII1_ETH1_CLK: J18.28 R359.2
CPSW_RGMII1_MDC: J18.20 R338.2 R342.2
CPSW_RGMII1_MDIO: J18.22 R340.2 R343.1
CPSW_RGMII1_RD0: J18.23 U136.W11(RGMII1_RD0)
CPSW_RGMII1_RD1: J18.25 U136.T11(RGMII1_RD1)
CPSW_RGMII1_RD2: J18.27 U136.T12(RGMII1_RD2)
CPSW_RGMII1_RD3: J18.29 U136.U12(RGMII1_RD3)
CPSW_RGMII1_RESETN: J18.12 R373.1 R5824.2 U68.4(Y)
CPSW_RGMII1_RX_DV: J18.45 U136.V12(RGMII1_RX_CTL)
CPSW_RGMII1_RXC: J18.19 U136.W12(RGMII1_RXC)
CPSW_RGMII1_TD0: J18.7 R530.2
CPSW_RGMII1_TD1: J18.9 R535.2
CPSW_RGMII1_TD2: J18.11 R537.2
CPSW_RGMII1_TD3: J18.13 R529.2
CPSW_RGMII1_TX_EN: J18.35 U136.T13(RGMII1_TX_CTL)
CPSW_RGMII1_TXC: J18.3 R239.2
CPSW_RGMII2_BCLK: J19.48 U29.2(A1)
CPSW_RGMII2_BCLK_1V8: U29.7(B1) U2347.1(NO0)
CPSW_RGMII2_BRD_CONN_DET: J19.36 R341.2
CPSW_RGMII2_COL: J19.14 TP588.1(TP)
CPSW_RGMII2_CRS: J19.30 TP589.1(TP)
CPSW_RGMII2_ETH2_CLK: J19.28 R358.2
CPSW_RGMII2_MDC: J19.20 R352.2 R356.2
CPSW_RGMII2_MDIO: J19.22 R345.2 R351.1
CPSW_RGMII2_RD0: J19.23 U136.U15(RGMII2_RD0)
CPSW_RGMII2_RD1: J19.25 U136.V15(RGMII2_RD1)
CPSW_RGMII2_RD2: J19.27 U136.W14(RGMII2_RD2)
CPSW_RGMII2_RD3: J19.29 U136.T15(RGMII2_RD3)
CPSW_RGMII2_RSTN: J19.12 R607.1 R5825.2 U120.4(Y)
CPSW_RGMII2_RX_DV: J19.45 U136.V14(RGMII2_RX_CTL)
CPSW_RGMII2_RXC: J19.19 U136.W15(RGMII2_RXC)
CPSW_RGMII2_TD0: J19.7 R509.2
CPSW_RGMII2_TD1: J19.9 R518.2
CPSW_RGMII2_TD2: J19.11 R527.2
CPSW_RGMII2_TD3: J19.13 R528.2
CPSW_RGMII2_TX_EN: J19.35 U136.U16(RGMII2_TX_CTL)
CPSW_RGMII2_TXC: J19.3 R228.2
CPSW_RGMII2_TXC_R: R228.1 U136.W17(RGMII2_TXC)
CPSW_RGMII_INTN: J18.10 R346.1 R620.1 R621.2
CPSW_RGMII_INTN_R: J19.10 R344.2 R346.2
CPSW_RGMII_TXC_R: R239.1 U136.V13(RGMII1_TXC)
DEBOUNCE_GPIO_INT_MCU_SOC: C489.2 D11.2 Q7.2(S) R559.2 SW5.2 SW5.3 U98.3(2A)
DEBOUNCE_IORET_WAKE: C3741.2 D18.2 R5756.2 SW10.2 SW10.3 U3070.2(A)
DEBOUNCE_MCU_RESETZ: C609.2 D12.2 Q12.2(S) R615.2 SW6.2 SW6.3 U98.1(1A)
DEBOUNCE_SOC_PORZ: C622.2 D14.2 R375.2 SW8.2 SW8.3 U98.6(3A)
DIR: R461.1 U81.2(DIR) U83.2(DIR)
DRAIN1: U129.8(DRAIN1_1) U129.15(DRAIN1_2) U129.19(DRAIN1_3) U129.58(DRAIN1_4)
DRAIN2: U129.7(DRAIN2_1) U129.52(DRAIN2_2) U129.56(DRAIN2_3) U129.57(DRAIN2_4)
ECAP0_IN_APWM_OUT: J13.11 R5685.1
ECAP1_IN_APWM_OUT: J12.9 U136.P2(SPI2_D0)
ECAP2_IN_APWM_OUT: J12.11 U136.R3(SPI2_D1)
ECAP3_IN_APWM_OUT: J13.9 U136.P4(GPIO1_48)
EEPROM_A1: R5745.2 U2358.2(A1)
EEPROM_A2: R5744.1 U2358.3(A2)
EEPROM_WP: J33.1 R5746.1 U2358.7(WP)
EMMC_CLK: R561.1 R565.2 U49.M6(CLK) U57.42(C0)
EMMC_CMD: R575.2 U49.M5(CMD) U57.22(C9)
EMMC_D0: R269.2 U49.A3(DAT0) U57.37(C2)
EMMC_D1: R266.2 U49.A4(DAT1) U57.35(C3)
